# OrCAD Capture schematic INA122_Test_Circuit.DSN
size A; title: INA122 Single Supply MicroPower Instrumentation Amplifier; rev: 1.1; note: Datasheet: SBOS069  EVM : N/A
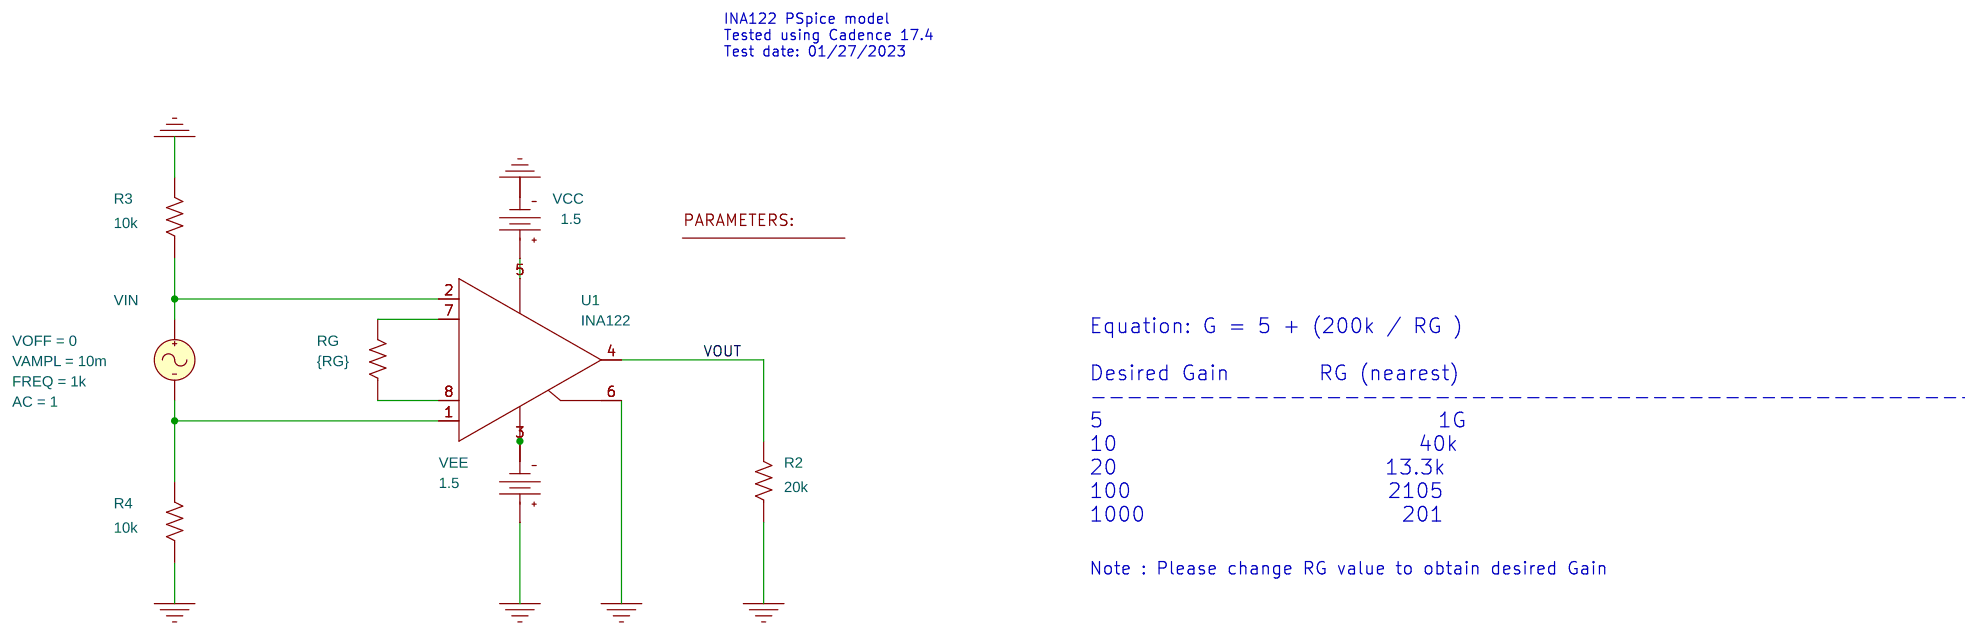
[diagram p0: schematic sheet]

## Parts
1  PARAM
R2  20k  [AX/RC05]
R3  10k  [AX/RC05]
R4  10k  [AX/RC05]
RG  {RG}  [AX/RC05]
U1  INA122
VCC  VDC
VEE  VDC
VIN  VSIN

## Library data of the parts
1 = PARAM: RG: 1G
R2-R4 RG = R
U1 = INA122
VCC VEE = VDC: DC: 1.5
VIN = VSIN: AC: 1; FREQ: 1k; VAMPL: 10m; VOFF: 0

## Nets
0: R2.1 R3.2 R4.1 U1.6(REF) VCC.1(-) VEE.0(+)
VOUT: R2.2 U1.4(OUT)
N14300126: RG.2 U1.7(RG+)
N14300130: RG.1 U1.8(RG-)
N14300699: U1.3(V-) VEE.1(-)
N14303202: U1.5(V+) VCC.0(+)
N14308525: R3.1 U1.2(-) VIN.1(+)
N14308573: R4.2 U1.1(+) VIN.2(-)

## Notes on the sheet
- INA122 PSpice model
  Tested using Cadence 17.4
  Test date: 01/27/2023
- Equation: G = 5 + (200k / RG )
  Desired Gain        RG (nearest)
  ----------------------------------------------------
  5                              1G
  10                           40k
  20                        13.3k
  100                       2105
  1000                       201
- Note : Please change RG value to obtain desired Gain
